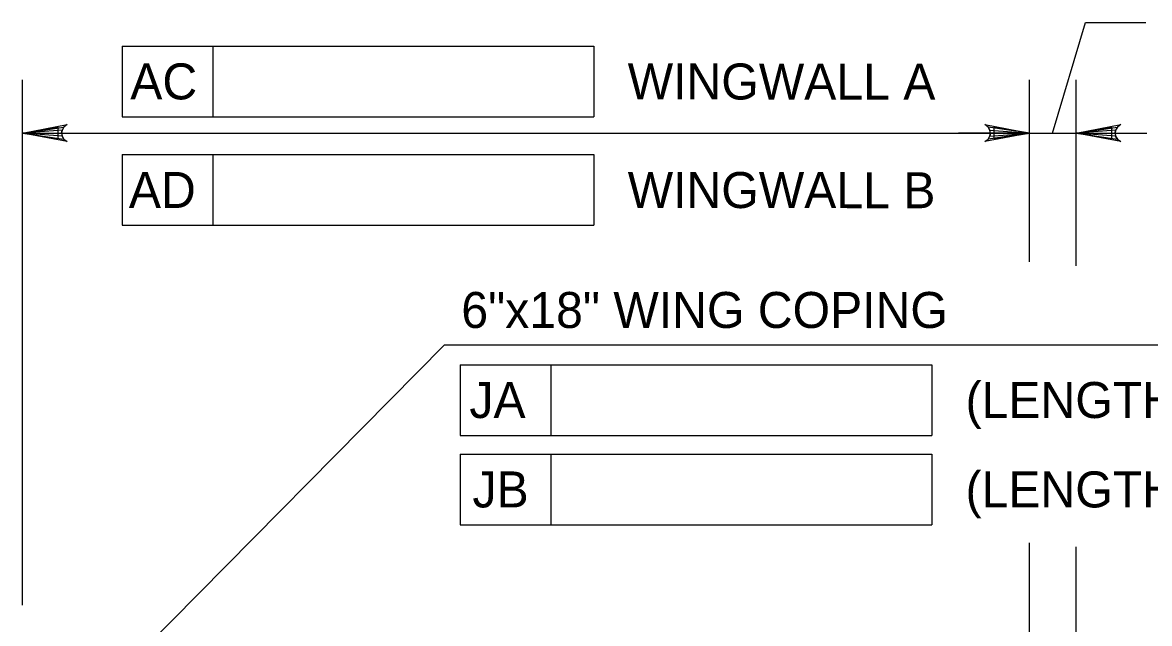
# Model space of a CAD drawing. Extents: x 638304 to 640306, y 296653 to 298435.
# Drawn here: x 639680.5 to 639774.4, y 297444.4 to 297494.4 of the extents above; entities that cross this region are included whole.
import ezdxf

# ---------------------------------------------------------------- set-up
doc = ezdxf.new("R2010")
doc.units = 0
doc.layers.add('Level 4', color=7, linetype='Continuous')
doc.layers.add('Level 5', color=7, linetype='Continuous')

msp = doc.modelspace()

# ---------------------------------------------------------------- linework, layer by layer
at = {"layer": 'Level 4'}
for p, q in [((639766.301, 297485.231), (639769.065, 297494.441)), ((639769.065, 297494.441), (639774.073, 297494.441)), ((639688.816, 297492.482), (639728.11, 297492.482)), ((639688.816, 297492.482), (639688.816, 297486.587)), ((639696.362, 297492.482), (639696.362, 297486.587)), ((639728.11, 297492.482), (639728.11, 297486.587)), ((639680.517, 297445.889), (639680.517, 297489.652)), ((639764.38, 297474.504), (639764.38, 297489.652)), ((639768.273, 297474.177), (639768.273, 297489.652)), ((639688.816, 297486.587), (639728.11, 297486.587)), ((639680.517, 297485.231), (639764.38, 297485.231)), ((639761.434, 297485.231), (639758.487, 297485.231)), ((639764.38, 297485.231), (639772.163, 297485.231)), ((639768.273, 297485.231), (639774.166, 297485.231)), ((639688.816, 297483.437), (639728.11, 297483.437)), ((639688.816, 297483.437), (639688.816, 297477.544)), ((639696.362, 297483.437), (639696.362, 297477.544)), ((639728.11, 297483.437), (639728.11, 297477.544)), ((639688.816, 297477.544), (639728.11, 297477.544)), ((639688.194, 297439.774), (639715.658, 297467.581)), ((639715.658, 297467.581), (639809.165, 297467.581)), ((639716.96, 297465.928), (639756.256, 297465.928)), ((639716.96, 297465.928), (639716.96, 297460.033)), ((639724.508, 297465.928), (639724.508, 297460.033)), ((639756.256, 297465.928), (639756.256, 297460.033)), ((639716.96, 297460.033), (639756.256, 297460.033)), ((639716.96, 297458.478), (639756.256, 297458.478)), ((639716.96, 297458.478), (639716.96, 297452.585)), ((639724.508, 297458.478), (639724.508, 297452.585)), ((639756.256, 297458.478), (639756.256, 297452.585)), ((639716.96, 297452.585), (639756.256, 297452.585)), ((639764.38, 297438.705), (639764.38, 297451.071)), ((639768.273, 297438.381), (639768.273, 297450.747))]:
    msp.add_line(p, q, dxfattribs=at)
for points in [[(639680.517, 297485.231), (639684.239, 297485.93), (639683.952, 297485.73), (639683.805, 297485.481), (639683.761, 297485.231), (639683.805, 297484.981), (639683.952, 297484.732), (639684.239, 297484.532), (639680.517, 297485.231), (639683.952, 297484.732), (639683.805, 297484.981), (639680.517, 297485.231), (639683.761, 297485.231), (639683.805, 297485.481), (639680.517, 297485.231), (639683.952, 297485.73)], [(639764.38, 297485.231), (639760.658, 297484.532), (639760.945, 297484.732), (639761.093, 297484.981), (639761.136, 297485.231), (639761.093, 297485.481), (639760.945, 297485.73), (639760.658, 297485.93), (639764.38, 297485.231), (639760.945, 297485.73), (639761.093, 297485.481), (639764.38, 297485.231), (639761.136, 297485.231), (639761.093, 297484.981), (639764.38, 297485.231), (639760.945, 297484.732)], [(639768.273, 297485.231), (639771.995, 297485.93), (639771.708, 297485.73), (639771.56, 297485.481), (639771.516, 297485.231), (639771.56, 297484.981), (639771.708, 297484.732), (639771.995, 297484.532), (639768.273, 297485.231), (639771.708, 297484.732), (639771.56, 297484.981), (639768.273, 297485.231), (639771.516, 297485.231), (639771.56, 297485.481), (639768.273, 297485.231), (639771.708, 297485.73)]]:
    msp.add_lwpolyline(points, dxfattribs=at)
for points in [[(639683.464, 297485.722), (639683.464, 297484.74), (639680.517, 297485.231)], [(639761.434, 297485.722), (639761.434, 297484.74), (639764.38, 297485.231)], [(639771.219, 297485.722), (639771.219, 297484.74), (639768.273, 297485.231)]]:
    msp.add_lwpolyline(points, close=True, dxfattribs=at)

# ---------------------------------------------------------------- texts
for s, p in [('AC', (639689.491, 297488.039)), ('WINGWALL A', (639730.921, 297488.035)), ('AD', (639689.373, 297478.994)), ('WINGWALL B', (639730.921, 297478.99))]:
    msp.add_text(s, height=3.0001, rotation=359.93823, dxfattribs=at).set_placement(p)
for s, height, p in [('(LENGTH) WINGWALL A', 3.00014, (639759.067, 297461.482)), ('JA', 3.0001, (639717.739, 297461.482)), ('(LENGTH) WINGWALL B', 3.00014, (639759.067, 297454.031)), ('JB', 3.0001, (639717.995, 297454.031))]:
    msp.add_text(s, height=height, dxfattribs=at).set_placement(p)
at = {"layer": 'Level 5'}
msp.add_text('6"x18" WING COPING', height=3.00014, dxfattribs=at).set_placement((639717.066, 297468.985))

doc.saveas('drawing.dxf')
